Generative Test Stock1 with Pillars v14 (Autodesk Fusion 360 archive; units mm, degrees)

design "Generative Test S1 w/ Pillars" references "HTR-1", "Sample Barreled Action"
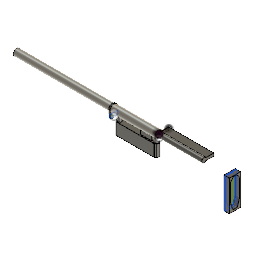
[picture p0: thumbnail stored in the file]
component_insert "Component Insert1"
sketch "Recoil Lug Surface" plane through (-203.2, 0, 0) normal (1, 0, 0) x axis (0, 0, -1)
  line L1 (33.02, 12.7909) -> (33.02, -12.7909)
  line L2 (0.4888, 16.8204) -> (29.9372, 15.9646)
  line L3 (29.9372, -15.9646) -> (0.4888, -16.8204)
  line L4 (31.75, 0) -> (15.24, 0)
  line L5 (31.75, 17.145) -> (31.75, 0)
  line L6 (15.24, 17.145) -> (31.75, 17.145)
  line L7 (15.24, 0) -> (15.24, 17.145)
  line L8 (15.24, 0) -> (15.24, -17.145)
  line L9 (15.24, -17.145) -> (31.75, -17.145)
  line L10 (31.75, -17.145) -> (31.75, 0)
  circle C1 centre (0, 0) radius 13.7795
  arc A1 centre (29.845, 12.7909) radius 3.175 clockwise from (29.9372, 15.9646) to (33.02, 12.7909)
  arc A2 centre (0, 0) radius 16.8275 clockwise from (0.4888, -16.8204) to (0.4888, 16.8204)
  arc A3 centre (29.845, -12.7909) radius 3.175 clockwise from (33.02, -12.7909) to (29.9372, -15.9646)
  point P11 (15.24, 0)
  point P16 (15.24, 0)
  point P12 (31.75, 0)
  point P18 (31.75, 0)
  point P13 (31.75, 17.145)
  point P17 (31.75, -17.145)
  point P14 (15.24, 17.145)
  point P15 (15.24, -17.145)
  point P1 (0, 0)
  horizontal L4
  vertical L5
  horizontal L6
  vertical L7
  symmetric P11 L4 P16
  symmetric P12 L4 P18
  symmetric P13 L4 P17
  symmetric P14 L4 P15
  dimension "d1" distance P11 P14 = 17.145
  dimension "d2" distance P13 P14 = 16.51
  dimension "d3" distance P1 P11 = 15.24
extrude "Extrude1" new body sketch "Recoil Lug Surface" profile of L1 A1 A3 L4 L5 L6 L7 L8 L9 L10 along normal blind 2.54 bodies "Recoil Lug Surface"
move "Move1"
component_insert "Component Insert2"
sketch "Recoil Pad" plane through (323.85, 0, 0) normal (1, 0, 0) x axis (0, 0, -1)
  line L1 (127, -25.4) -> (-12.7, -25.4)
  line L2 (127, 25.4) -> (127, -25.4)
  line L3 (-12.7, 25.4) -> (127, 25.4)
  line L4 (-12.7, -25.4) -> (-12.7, 25.4)
  horizontal L1
  vertical L2
  horizontal L3
  vertical L4
extrude "Extrude3" new body sketch "Recoil Pad" against normal blind 6.35 bodies "Shoulder Surface"
extrude "Extrude4" new body sketch "Recoil Pad" along normal blind 25.4
move "Move2"
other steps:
step "́   Ā  $ 62e3f451-2bba-4a55-b460-13f280e31624␀ 䔀㌰㠷䔴ⵄ䔵㤱㐭ㅅⴴ㥂㉆㌭あ〷㜱㄰䌸⑄ 愀　㠀㌀挀　㔀㌀ⴀ昀戀昀㈀ⴀ㐀　戀㜀ⴀ戀㐀㐀戀ⴀ㌀　㜀㘀昀搀㠀㘀㄀㄀搀挀Ā$ f480cb37-e8ac-4f28-8014-b285c51c4120< urn:adsk.wipprod:fs.file:vf.4uMgOVTCShKSCh-cCJd_8A?ver" bodies "Recoil Lug Surface", "Shoulder Surface"
named bodies: "Recoil Lug Surface", "Shoulder Surface"

design "Sample M700 Trigger"
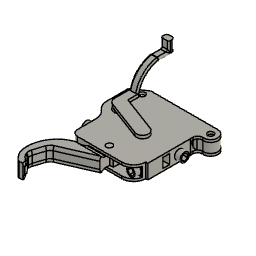
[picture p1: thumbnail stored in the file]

design "Sample Barreled Action" references "Sample M700 Trigger"
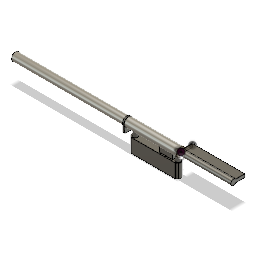
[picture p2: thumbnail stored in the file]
sketch "Receiver Body" plane through (0, 0, 0) normal (1, 0, 0) x axis (0, 0, -1)
  circle C1 centre (0, 0) radius 17.145
  point P1 (0, 0)
  point P2 (0, 0)
  coincident P1 P2
  dimension "d1" diameter C1 = 34.29
extrude "Extrude1" new body sketch "Receiver Body" against normal blind 203.2 bodies "Receiver"
work_plane "WorkPlane1" AlongDistance 6.35
sketch "BARREL" plane through (-209.55, 0, 0) normal (-1, 0, 0) x axis (0, 0, -1)
  circle C1 centre (0, 0) radius 15.875
  point P1 (0, 0)
  point P2 (0, 0)
  coincident P1 P2
  dimension "d5" diameter C1 = 31.75
extrude "Extrude2" new body sketch "BARREL" along normal blind 431.8 bodies "Barrel"
sketch "Rear Receiver Screw" plane through (0, 0, 0) normal (0, 1, 0) x axis (1, 0, 0)
  circle C1 centre (0, 0) radius 3.81
  point P1 (0, 0)
  point P2 (0, 0)
  coincident P1 P2
  dimension "d8" diameter C1 = 7.62
extrude "Extrude3" new body sketch "Rear Receiver Screw" against normal blind 25.4 bodies "Rear Action Screw Hole Tool"
move "Move1"
sketch "Sketch4" plane through (0, 0, 0) normal (0, 0, 1) x axis (1, 0, 0)
  circle C1 centre (0, -13.97) radius 1.5875
  dimension "d11" diameter C1 = 3.175
extrude "Extrude4" new body sketch "Sketch4" distance 7.62 bodies "Rear Trigger Pin Tool"
move "Move2"
copy_paste_bodies "CopyPasteBodies1"
move "Move3"
component_insert "Component Insert"
copy_paste_bodies "CopyPasteBodies2"
move "Move4"
move "Move5"
move "Move6"
position "Position1"
work_plane "WorkPlane2" AlongDistance 0
sketch "Sketch5" plane through (-203.2, 0, 0) normal (-1, 0, 0) x axis (0, 1, 0)
  line L1 (-33.02, 12.7909) -> (-33.02, 0)
  line L2 (-0.4888, 16.8204) -> (-29.9372, 15.9646)
  line L3 (-0.4888, -16.8204) -> (-29.9372, -15.9646)
  line L4 (-33.02, -12.7909) -> (-33.02, 0)
  circle C1 centre (0, 0) radius 16.8275
  circle C2 centre (0, 0) radius 13.7795
  arc A1 centre (-29.845, -12.7909) radius 3.175 clockwise from (-29.9372, -15.9646) to (-33.02, -12.7909)
  arc A2 centre (-29.845, 12.7909) radius 3.175 clockwise from (-33.02, 12.7909) to (-29.9372, 15.9646)
  point P1 (0, 0)
  point P2 (0, 0)
  point P5 (-0.4888, 16.8204)
  point P6 (0, 0)
  point P4 (-33.02, 15.875)
  point P3 (-33.02, 0)
  coincident P1 P2
  vertical L1
  coincident C1 P5
  tangent C1 L2
  coincident P1 P6
  tangent L3 A1
  tangent L4 A1
  coincident P4 L1
  coincident P4 L2
  tangent L1 A2
  tangent L2 A2
  equal A1 A2
  dimension "d22" diameter C1 = 33.655
  dimension "d23" distance P3 P4 = 15.875
  dimension "d24" diameter C2 = 27.559
  dimension "d25" radius A1 = 3.175
extrude "Extrude5" new body sketch "Sketch5" along normal blind 6.35 bodies "Recoil Lug"
sketch "Bolt and Handle" plane through (0, 0, 0) normal (1, 0, 0) x axis (0, 0, -1)
  line L1 (44.45, 0) -> (0, 0)
  line L2 (44.45, 6.35) -> (44.45, 0)
  line L3 (0, 6.35) -> (44.45, 6.35)
  line L4 (0, 0) -> (0, 6.35)
  line L5 (0, -6.35) -> (44.45, -6.35)
  line L6 (0, 0) -> (0, -6.35)
  line L7 (44.45, -6.35) -> (44.45, 0)
  circle C1 centre (0, 0) radius 17.145
  circle C2 centre (0, 0) radius 10.795
  point P3 (0, 0)
  point P4 (0, 0)
  point P10 (0, 0)
  point P5 (44.45, 0)
  point P11 (44.45, 0)
  point P6 (44.45, 6.35)
  point P8 (44.45, -6.35)
  point P7 (0, 6.35)
  point P9 (0, -6.35)
  concentric C1 C2
  horizontal L1
  vertical L2
  horizontal L3
  vertical L4
  coincident P3 P4
  symmetric P4 L1 P10
  symmetric P5 L1 P11
  symmetric P6 L1 P8
  symmetric P7 L1 P9
  dimension "d28" diameter C2 = 21.59
  dimension "d29" distance P4 P5 = 44.45
  dimension "d30" distance P4 P7 = 6.35
extrude "Extrude6" new body sketch "Bolt and Handle" against normal blind 12.7 bodies "Bolt Handle"
move "Move7"
move "Move8"
extrude "Extrude7" new body sketch "Bolt and Handle" along normal blind 203.2 bodies "Bolt and Handle Clearance"
sketch "Pillar" plane through (0, 0, 0) normal (0, 1, 0) x axis (-1, 0, 0)
  circle C1 centre (11.557, 0) radius 3.81
  circle C2 centre (11.557, 0) radius 8.5725
  concentric C1 C2
  dimension "d35" diameter C2 = 17.145
extrude "Extrude8" new body sketch "Pillar" against normal blind 50.8 bodies "Rear Pillar"
copy_paste_bodies "CopyPasteBodies3"
move "Move9"
sketch "Maximal bottom metal" plane through (0, -50.8, 0) normal (0, -1, 0) x axis (1, 0, 0)
  line L1 (-9.017, 0) -> (-181.737, 0)
  line L2 (-9.017, 12.5116) -> (-9.017, 0)
  line L3 (-180.777, 12.7) -> (-9.977, 12.7)
  line L4 (-181.737, 0) -> (-181.737, 12.5116)
  line L5 (-188.0372, 7.1437) -> (-182.457, 12.065)
  line L6 (-2.7168, 7.1437) -> (-8.297, 12.065)
  line L7 (-188.0372, -7.1437) -> (-182.457, -12.065)
  line L8 (-180.777, -12.7) -> (-9.977, -12.7)
  line L9 (-2.7168, -7.1437) -> (-8.297, -12.065)
  circle C1 centre (-11.557, 0) radius 3.81
  circle C2 centre (-11.557, 0) radius 8.5725
  circle C3 centre (-9.017, 0) radius 9.525
  circle C4 centre (-181.737, 0) radius 9.525
  arc A1 centre (-180.777, 10.16) radius 2.54 clockwise from (-182.457, 12.065) to (-180.777, 12.7)
  arc A2 centre (-9.977, 10.16) radius 2.54 clockwise from (-9.977, 12.7) to (-8.297, 12.065)
  arc A3 centre (-180.777, -10.16) radius 2.54 clockwise from (-180.777, -12.7) to (-182.457, -12.065)
  arc A4 centre (-9.977, -10.16) radius 2.54 clockwise from (-8.297, -12.065) to (-9.977, -12.7)
  point P4 (-181.737, 0)
  point P5 (-181.737, 0)
  point P7 (-188.0372, 7.1437)
  point P8 (-2.7168, 7.1437)
  point P15 (-181.737, 12.5116)
  point P16 (-9.017, 12.5116)
  point P18 (-188.0372, -7.1437)
  point P24 (-2.7168, -7.1437)
  point P9 (-182.457, 12.065)
  point P17 (-182.457, -12.065)
  point P10 (-180.777, 12.7)
  point P20 (-180.777, -12.7)
  point P12 (-9.977, 12.7)
  point P21 (-9.977, -12.7)
  point P13 (-8.297, 12.065)
  point P23 (-8.297, -12.065)
  point P6 (-9.017, 0)
  horizontal L1
  vertical L2
  horizontal L3
  vertical L4
  coincident P4 P5
  coincident C4 P7
  tangent C4 L5
  coincident C3 P8
  tangent C3 L6
  tangent L5 A1
  tangent L3 A1
  tangent L3 A2
  tangent L6 A2
  equal A1 A2
  coincident A1 P15
  coincident A2 P16
  symmetric L1 P7 P18
  symmetric L1 P8 P24
  symmetric L1 P9 P17
  symmetric L1 P10 P20
  symmetric L1 A1 A3
  symmetric L1 P12 P21
  symmetric L1 P13 P23
  symmetric L1 A2 A4
  dimension "d38" diameter C3 = 19.05
  dimension "d39" diameter C4 = 19.05
  dimension "d41" distance P5 P6 = 172.72
  dimension "d42" radius A1 = 2.54
extrude "Extrude9" new body sketch "Maximal bottom metal" against normal blind 25.4 bodies "Maximal Bottom Metal"
move "Move10"
move "Move11"
split "Split1" bodies "Front Pillar", "Rear Pillar"
remove_body "RemoveBody1"
remove_body "RemoveBody2"
offset_faces "OffsetFaces1" distance -19.177
offset_faces "OffsetFaces2" distance -28.067
offset_faces "OffsetFaces3" distance 3.175
combine "Combine1"
offset_faces "OffsetFaces4" distance 50.8
offset_faces "OffsetFaces5" distance 50.8
combine "Combine2"
sketch "Sketch9" plane through (0, -34.925, 0) normal (0, 1, 0) x axis (-1, 0, 0)
  line L1 (180.777, -12.7) -> (9.977, -12.7)
  line L2 (188.0372, -7.1437) -> (182.457, -12.065)
  line L3 (182.457, 12.065) -> (188.0372, 7.1437)
  line L4 (9.977, 12.7) -> (180.777, 12.7)
  line L5 (2.7168, 7.1437) -> (8.297, 12.065)
  line L6 (8.297, -12.065) -> (2.7168, -7.1437)
  line L7 (25.4, -7.62) -> (76.2, -7.62)
  line L8 (25.4, 7.62) -> (25.4, -7.62)
  line L9 (76.2, 7.62) -> (25.4, 7.62)
  line L10 (76.2, -7.62) -> (76.2, 7.62)
  circle C1 centre (11.557, 0) radius 8.5725
  arc A1 centre (9.977, -10.16) radius 2.54 clockwise from (9.977, -12.7) to (8.297, -12.065)
  arc A2 centre (180.777, -10.16) radius 2.54 clockwise from (182.457, -12.065) to (180.777, -12.7)
  arc A3 centre (181.737, 0) radius 9.525 clockwise from (188.0372, 7.1437) to (188.0372, -7.1437)
  arc A4 centre (180.777, 10.16) radius 2.54 clockwise from (180.777, 12.7) to (182.457, 12.065)
  arc A5 centre (9.977, 10.16) radius 2.54 clockwise from (8.297, 12.065) to (9.977, 12.7)
  arc A6 centre (9.017, 0) radius 9.525 clockwise from (2.7168, -7.1437) to (2.7168, 7.1437)
  circle C2 centre (176.53, 0) radius 8.5725
  horizontal L7
  vertical L8
  horizontal L9
  vertical L10
extrude "Extrude10" new body sketch "Sketch9" profile of L7 L8 L9 L10 along normal blind 25.4 bodies "Trigger Clearance"
offset_faces "OffsetFaces6" distance 12.7
offset_faces "OffsetFaces7" distance 12.7
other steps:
base_feature "Base Feature1" bodies "Rear Trigger Pin Tool", "Front Trigger Pin Tool"
base_feature "Base Feature2" bodies "Rear Action Screw Hole Tool", "Front Action Screw Hole Tool"
base_feature "Base Feature3" bodies "Rear Pillar", "Front Pillar"
named bodies: "Receiver", "Barrel", "Rear Action Screw Hole Tool", "Rear Trigger Pin Tool", "Front Trigger Pin Tool", "Front Action Screw Hole Tool", "Recoil Lug", "Bolt Handle", "Bolt and Handle Clearance", "Rear Pillar", "Front Pillar", "Maximal Bottom Metal", "Trigger Clearance"

design "Blank"
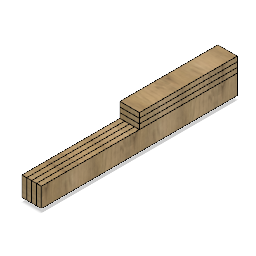
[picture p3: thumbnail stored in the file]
sketch "4x40 Paulownia" plane through (0, 0, 0) normal (1, 0, 0) x axis (0, 0, -1)
  dimension "d1" = 1016
  dimension "d2" = 101.6
extrude "Extrude1" new body sketch "4x40 Paulownia" along normal blind 25.4
copy_paste_bodies "CopyPasteBodies1"
move "Move1"
copy_paste_bodies "CopyPasteBodies2"
move "Move2"
move "Move3"
mesh "Mesh1"
sketch "4x20 Paulownia" plane through (0, 0, 0) normal (1, 0, 0) x axis (0, 0, -1)
  dimension "d5" = 508
  dimension "d6" = 101.6
extrude "Extrude2" new body sketch "4x20 Paulownia" along normal blind 25.4
move "Move7"
copy_paste_bodies "CopyPasteBodies6"
move "Move8"
copy_paste_bodies "CopyPasteBodies7"
move "Move9"
copy_paste_bodies "CopyPasteBodies8"
move "Move10"
move "Move11"
sketch "2x10 Walnut" plane through (0, 0, 0) normal (1, 0, 0) x axis (0, 0, -1)
  dimension "d9" = 254
  dimension "d10" = 50.8
extrude "Extrude3" new body sketch "2x10 Walnut" along normal blind 38.1 bodies "Walnut Receiver Block (2  x 10  x 1.5 )"
move "Move12"
combine "Combine1"
combine "Combine2"
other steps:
base_feature "Base Feature1"
base_feature "Base Feature2"
base_feature "Base Feature6"
base_feature "Base Feature7"
base_feature "Base Feature8"
named bodies: "Walnut Receiver Block (2  x 10  x 1.5 )"

design "HTR-1" references "Sample Barreled Action", "Blank"
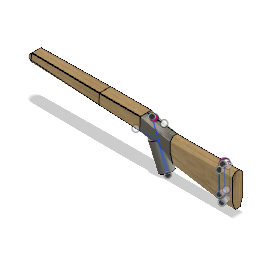
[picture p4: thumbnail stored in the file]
work_plane "WorkPlane1" AlongDistance -31.75
sketch "Forend - Rear" plane through (-31.75, 0, 0) normal (1, 0, 0) x axis (0, 0, -1)
  line L1 (0, -50.8) -> (0, 0)
  line L2 (-21.3309, 0) -> (0, 0)
  line L3 (-24.765, -50.8) -> (0, -50.8)
  line L4 (-24.8387, -52.764) -> (-22.9173, -1.528)
  line L5 (21.3309, 0) -> (0, 0)
  line L6 (24.8387, -52.764) -> (22.9173, -1.528)
  line L7 (24.765, -50.8) -> (0, -50.8)
  arc A1 centre (-21.3309, -1.5875) radius 1.5875 clockwise from (-22.9173, -1.528) to (-21.3309, 0)
  arc A2 centre (21.3309, -1.5875) radius 1.5875 clockwise from (21.3309, 0) to (22.9173, -1.528)
  point P1 (0, 0)
  point P2 (0, 0)
  point P4 (0, 0)
  point P5 (-22.86, 0)
  point P6 (-24.765, -50.8)
  point P3 (0, -50.8)
  point P16 (0, -50.8)
  point P12 (0, 0)
  point P7 (-21.3309, 0)
  point P13 (21.3309, 0)
  point P8 (-22.9173, -1.528)
  point P14 (22.9173, -1.528)
  point P10 (-24.8387, -52.764)
  point P15 (24.8387, -52.764)
  point P11 (-24.765, -50.8)
  point P17 (24.765, -50.8)
  coincident P1 P2
  vertical L1
  coincident P1 P4
  perpendicular L1 L2
  perpendicular L1 L3
  coincident P5 L2
  coincident P5 L4
  tangent L2 A1
  tangent L4 A1
  coincident P6 L4
  coincident P6 L3
  symmetric P3 L1 P16
  symmetric L1 P4 P12
  symmetric L1 P7 P13
  symmetric L1 P8 P14
  symmetric L1 A1 A2
  symmetric L1 P10 P15
  symmetric L1 P11 P17
  coincident P6 P11
  dimension "d8" distance P2 P3 = 50.8
  dimension "d9" distance P4 P5 = 22.86 (= "( 1.8 / 2 ) * 1 in")
  dimension "d10" distance P3 P6 = 24.765 (= "( 1.95 / 2 ) * 1 in")
  dimension "d11" radius A1 = 1.5875 (= "( 0.125 / 2 ) * 1 in")
work_plane "WorkPlane2" AlongDistance -190.5
extrude "Extrude1" new body sketch "Forend - Rear" against normal blind 158.75
work_plane "WorkPlane3" RotateAngle 3
split "Split1" bodies "Forend - Receiver"
remove_body "RemoveBody1"
fillet "Fillet1" radius 3.175
work_plane "WorkPlane4" AlongDistance -266.7
sketch "Forend - Front" plane through (-457.2, 0, 0) normal (1, 0, 0) x axis (0, 0, -1)
  line L1 (0, -37.465) -> (0, 0)
  line L2 (-8.684, -37.465) -> (0, -37.465)
  line L3 (-17.3103, 0) -> (0, 0)
  line L4 (-21.3076, -23.3743) -> (-18.8882, -1.4137)
  line L5 (17.3103, 0) -> (0, 0)
  line L6 (21.3076, -23.3743) -> (18.8882, -1.4137)
  line L7 (8.684, -37.465) -> (0, -37.465)
  arc A1 centre (-17.3103, -1.5875) radius 1.5875 clockwise from (-18.8882, -1.4137) to (-17.3103, 0)
  arc A2 centre (-8.684, -24.765) radius 12.7 clockwise from (-8.684, -37.465) to (-21.3076, -23.3743)
  arc A3 centre (17.3103, -1.5875) radius 1.5875 clockwise from (17.3103, 0) to (18.8882, -1.4137)
  arc A4 centre (8.684, -24.765) radius 12.7 clockwise from (21.3076, -23.3743) to (8.684, -37.465)
  point P5 (-18.7325, 0)
  point P4 (-22.86, -37.465)
  point P2 (0, 0)
  point P12 (0, 0)
  point P3 (0, -37.465)
  point P19 (0, -37.465)
  point P6 (-17.3103, 0)
  point P13 (17.3103, 0)
  point P7 (-18.8882, -1.4137)
  point P14 (18.8882, -1.4137)
  point P9 (-21.3076, -23.3743)
  point P15 (21.3076, -23.3743)
  point P10 (-8.684, -37.465)
  point P18 (8.684, -37.465)
  vertical L1
  perpendicular L1 L2
  perpendicular L1 L3
  coincident P5 L3
  coincident P5 L4
  tangent L3 A1
  tangent L4 A1
  coincident P4 L4
  coincident P4 L2
  tangent L4 A2
  tangent L2 A2
  symmetric P2 L1 P12
  symmetric P3 L1 P19
  symmetric L1 P6 P13
  symmetric L1 P7 P14
  symmetric L1 A1 A3
  symmetric L1 P9 P15
  symmetric L1 P10 P18
  symmetric L1 A2 A4
  dimension "d19" distance P2 P3 = 37.465
  dimension "d20" distance P3 P4 = 22.86 (= "1.8 in / 2")
  dimension "d21" distance P2 P5 = 18.7325 (= "1.475 in / 2")
  dimension "d22" radius A1 = 1.5875 (= "( 0.125 / 2 ) * 1 in")
  dimension "d23" radius A2 = 12.7
loft "Loft1" sketch "Forend - Front"
revolve "Revolve1" sketch "Forend - Front" AlongAngle -180
work_plane "WorkPlane6" RotateAngle 45
split "Split3"
surface_patch "SurfacePatch1"
surface_patch "SurfacePatch2"
work_plane "WorkPlane7" AlongDistance 82.55 (= "-1.25 in + 4.5 in")
sketch "Buttstock - Front" plane through (82.55, 0, 0) normal (1, 0, 0) x axis (0, 0, -1)
  line L1 (0, -110.49) -> (0, -15.24)
  line L2 (-20.32, -64.607) -> (-20.32, -30.5703)
  line L3 (-6.9624, -15.24) -> (0, -15.24)
  line L4 (-18.4601, -26.0801) -> (-8.085, -15.705)
  line L5 (-8.8944, -110.49) -> (0, -110.49)
  line L6 (-10.442, -109.2562) -> (-20.0007, -67.4369)
  line L7 (6.9624, -15.24) -> (0, -15.24)
  line L8 (18.4601, -26.0801) -> (8.085, -15.705)
  line L9 (20.32, -64.607) -> (20.32, -30.5703)
  line L10 (10.442, -109.2562) -> (20.0007, -67.4369)
  line L11 (8.8944, -110.49) -> (0, -110.49)
  arc A1 centre (-8.8944, -108.9025) radius 1.5875 clockwise from (-8.8944, -110.49) to (-10.442, -109.2562)
  arc A2 centre (-6.9624, -16.8275) radius 1.5875 clockwise from (-8.085, -15.705) to (-6.9624, -15.24)
  arc A3 centre (-13.97, -30.5703) radius 6.35 clockwise from (-20.32, -30.5703) to (-18.4601, -26.0801)
  arc A4 centre (-7.62, -64.607) radius 12.7 clockwise from (-20.0007, -67.4369) to (-20.32, -64.607)
  arc A5 centre (6.9624, -16.8275) radius 1.5875 clockwise from (6.9624, -15.24) to (8.085, -15.705)
  arc A6 centre (13.97, -30.5703) radius 6.35 clockwise from (18.4601, -26.0801) to (20.32, -30.5703)
  arc A7 centre (7.62, -64.607) radius 12.7 clockwise from (20.32, -64.607) to (20.0007, -67.4369)
  arc A8 centre (8.8944, -108.9025) radius 1.5875 clockwise from (10.442, -109.2562) to (8.8944, -110.49)
  point P7 (-10.16, -110.49)
  point P6 (-7.62, -15.24)
  point P4 (-20.32, -27.94)
  point P5 (-20.32, -66.04)
  point P2 (0, -15.24)
  point P20 (0, -15.24)
  point P3 (0, -110.49)
  point P33 (0, -110.49)
  point P8 (-8.8944, -110.49)
  point P32 (8.8944, -110.49)
  point P9 (-10.442, -109.2562)
  point P29 (10.442, -109.2562)
  point P11 (-6.9624, -15.24)
  point P21 (6.9624, -15.24)
  point P12 (-8.085, -15.705)
  point P23 (8.085, -15.705)
  point P14 (-20.32, -30.5703)
  point P26 (20.32, -30.5703)
  point P15 (-18.4601, -26.0801)
  point P24 (18.4601, -26.0801)
  point P17 (-20.32, -64.607)
  point P27 (20.32, -64.607)
  point P18 (-20.0007, -67.4369)
  point P28 (20.0007, -67.4369)
  point P1 (0, 0)
  vertical L1
  vertical L2
  perpendicular L1 L3
  perpendicular L1 L5
  coincident P7 L5
  coincident P7 L6
  tangent L5 A1
  tangent L6 A1
  coincident P6 L3
  coincident P6 L4
  tangent L3 A2
  tangent L4 A2
  coincident P4 L2
  coincident P4 L4
  tangent L2 A3
  tangent L4 A3
  coincident P5 L2
  coincident P5 L6
  tangent L2 A4
  tangent L6 A4
  symmetric P2 L1 P20
  symmetric P3 L1 P33
  symmetric L1 P8 P32
  symmetric L1 P9 P29
  symmetric L1 A1 A8
  symmetric L1 P11 P21
  symmetric L1 P12 P23
  symmetric L1 A2 A5
  symmetric L1 P14 P26
  symmetric L1 P15 P24
  symmetric L1 A3 A6
  symmetric L1 P17 P27
  symmetric L1 P18 P28
  symmetric L1 A4 A7
  dimension "d29" distance P2 P3 = 95.25
  dimension "d30" distance P1 P2 = 15.24
  dimension "d31" distance L1 L2 = 20.32
  dimension "d32" distance P2 P4 = 12.7
  dimension "d33" distance P4 P5 = 38.1
  dimension "d34" distance P2 P6 = 7.62
  dimension "d35" distance P3 P7 = 10.16
  dimension "d36" radius A1 = 1.5875 (= "( 0.125 / 2 ) * 1 in")
  dimension "d37" radius A2 = 1.5875 (= "( 0.125 / 2 ) * 1 in")
  dimension "d38" radius A3 = 6.35
  dimension "d39" radius A4 = 12.7
work_plane "WorkPlane8" AlongDistance 273.05 (= "3.25 in + 7.5 in")
sketch "Buttstock - Rear" plane through (273.05, 0, 0) normal (1, 0, 0) x axis (0, 0, -1)
  line L1 (0, -142.24) -> (0, -15.24)
  line L2 (-6.9624, -15.24) -> (0, -15.24)
  line L3 (-9.0012, -142.24) -> (0, -142.24)
  line L4 (-20.32, -108.5075) -> (-20.32, -30.5703)
  line L5 (-8.085, -15.705) -> (-18.4601, -26.0801)
  line L6 (-10.5132, -141.1363) -> (-19.7158, -112.3782)
  line L7 (20.32, -108.5075) -> (20.32, -30.5703)
  line L8 (10.5132, -141.1363) -> (19.7158, -112.3782)
  line L9 (9.0012, -142.24) -> (0, -142.24)
  line L10 (8.085, -15.705) -> (18.4601, -26.0801)
  line L11 (6.9624, -15.24) -> (0, -15.24)
  arc A1 centre (-6.9624, -16.8275) radius 1.5875 clockwise from (-8.085, -15.705) to (-6.9624, -15.24)
  arc A2 centre (-9.0012, -140.6525) radius 1.5875 clockwise from (-9.0012, -142.24) to (-10.5132, -141.1363)
  arc A3 centre (-13.97, -30.5703) radius 6.35 clockwise from (-20.32, -30.5703) to (-18.4601, -26.0801)
  arc A4 centre (-7.62, -108.5075) radius 12.7 clockwise from (-19.7158, -112.3782) to (-20.32, -108.5075)
  arc A5 centre (6.9624, -16.8275) radius 1.5875 clockwise from (6.9624, -15.24) to (8.085, -15.705)
  arc A6 centre (13.97, -30.5703) radius 6.35 clockwise from (18.4601, -26.0801) to (20.32, -30.5703)
  arc A7 centre (7.62, -108.5075) radius 12.7 clockwise from (20.32, -108.5075) to (19.7158, -112.3782)
  arc A8 centre (9.0012, -140.6525) radius 1.5875 clockwise from (10.5132, -141.1363) to (9.0012, -142.24)
  point P4 (-7.62, -15.24)
  point P5 (-10.16, -142.24)
  point P6 (-20.32, -27.94)
  point P7 (-20.32, -110.49)
  point P2 (0, -15.24)
  point P29 (0, -15.24)
  point P3 (0, -142.24)
  point P25 (0, -142.24)
  point P9 (-6.9624, -15.24)
  point P30 (6.9624, -15.24)
  point P10 (-8.085, -15.705)
  point P28 (8.085, -15.705)
  point P12 (-9.0012, -142.24)
  point P26 (9.0012, -142.24)
  point P13 (-10.5132, -141.1363)
  point P24 (10.5132, -141.1363)
  point P15 (-20.32, -30.5703)
  point P21 (20.32, -30.5703)
  point P16 (-18.4601, -26.0801)
  point P27 (18.4601, -26.0801)
  point P18 (-20.32, -108.5075)
  point P22 (20.32, -108.5075)
  point P19 (-19.7158, -112.3782)
  point P23 (19.7158, -112.3782)
  point P1 (0, 0)
  point P8 (0, -15.24)
  vertical L1
  perpendicular L1 L2
  perpendicular L1 L3
  vertical L4
  coincident P4 L2
  coincident P4 L5
  tangent L2 A1
  tangent L5 A1
  coincident P5 L3
  coincident P5 L6
  tangent L3 A2
  tangent L6 A2
  coincident P6 L4
  coincident P6 L5
  tangent L4 A3
  tangent L5 A3
  coincident P7 L4
  coincident P7 L6
  tangent L4 A4
  tangent L6 A4
  symmetric P2 L1 P29
  symmetric P3 L1 P25
  symmetric L1 P9 P30
  symmetric L1 P10 P28
  symmetric L1 A1 A5
  symmetric L1 P12 P26
  symmetric L1 P13 P24
  symmetric L1 A2 A8
  symmetric L1 P15 P21
  symmetric L1 P16 P27
  symmetric L1 A3 A6
  symmetric L1 P18 P22
  symmetric L1 P19 P23
  symmetric L1 A4 A7
  dimension "d41" distance P2 P3 = 127
  dimension "d42" distance P1 P2 = 15.24
  dimension "d43" distance P2 P4 = 7.62
  dimension "d44" distance P3 P5 = 10.16
  dimension "d45" distance P6 P7 = 82.55
  dimension "d46" distance P6 P8 = 12.7
  dimension "d47" radius A1 = 1.5875 (= "( 0.125 / 2 ) * 1 in")
  dimension "d48" radius A2 = 1.5875 (= "( 0.125 / 2 ) * 1 in")
  dimension "d49" radius A3 = 6.35
  dimension "d50" radius A4 = 12.7
loft "Loft2" sketch "Buttstock - Front" + "Buttstock - Rear" bodies "Buttstock"
remove_body "RemoveBody3"
extrude "Extrude2" add of existing geometry blind 50.8
canvas "Canvas1"
canvas "Canvas2"
sketch "Grip Angle" plane through (0, 0, 0) normal (0, 0, 1) x axis (1, 0, 0)
  line L1 (59.5688, -165.1) -> (-11.4851, 0)
  line L2 (45.22, -165.1) -> (-5.9078, 0)
  line L3 (-5.9078, 0) -> (-11.4851, 0)
  line L4 (59.5688, -165.1) -> (45.22, -165.1)
  line L5 (52.3944, -165.1) -> (-8.6965, 0)
  line L6 (38.1, 0) -> (0, 0)
  line L7 (-71.3905, -70.8225) -> (17.5095, -70.8225)
  point P6 (-8.6965, 0)
  point P7 (52.3944, -165.1)
  point P8 (-8.6965, 0)
  point P9 (52.3944, -165.1)
  point P1 (0, 0)
  point P10 (0, 0)
  point P12 (17.5095, -70.8225)
  point P13 (-71.3905, -70.8225)
  horizontal L3
  horizontal L4
  midpoint L3 P6
  midpoint L4 P7
  coincident P6 P8
  coincident P7 P9
  coincident P1 P10
  horizontal L6
  coincident L5 P12
  horizontal L7
  dimension "d54" distance P12 P13 = 88.9
component_insert "Component Insert1"
work_axis "WorkAxis1"
work_plane "WorkPlane9"
work_plane "WorkPlane10" AlongDistance -114.3
work_plane "WorkPlane11" AlongDistance -12.7
work_plane "WorkPlane12" AlongDistance -25.4
sketch "Sketch11" plane through (12.7291, -57.9032, 0) normal (0.347, -0.9379, 0) x axis (0.9379, 0.347, 0)
  circle C1 centre (0, 0) radius 28.575
  point P1 (0, 0)
  point P2 (0, 0)
  coincident P1 P2
  dimension "d59" diameter C1 = 57.15
sketch "Sketch12" plane through (47.9871, -153.1892, 0) normal (0.347, -0.9379, 0) x axis (0.9379, 0.347, 0)
  circle C1 centre (0, 0) radius 25.4
  point P1 (0, 0)
  point P2 (0, 0)
  coincident P1 P2
  dimension "d60" diameter C1 = 50.8
loft "Loft3" sketch "Sketch11" + "Sketch12"
loft "Loft4"
component_insert "Component Insert2"
work_plane "WorkPlane5" RotateAngle 35
split "Split2"
remove_body "RemoveBody2"
named bodies: "Forend - Receiver", "Buttstock"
